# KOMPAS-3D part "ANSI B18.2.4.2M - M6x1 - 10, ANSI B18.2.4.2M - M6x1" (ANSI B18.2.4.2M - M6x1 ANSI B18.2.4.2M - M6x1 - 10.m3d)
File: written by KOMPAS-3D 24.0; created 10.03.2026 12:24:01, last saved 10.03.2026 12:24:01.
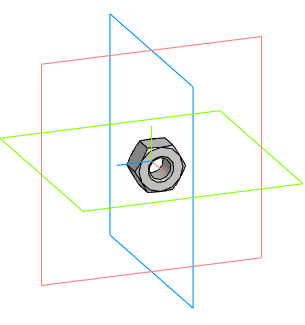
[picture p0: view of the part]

Document properties: Автор: R2D2; Полное имя файла: E:\Работа\Зайцев\BV3232P(4pc)-FP-3WL-F-ISO-H Кран шаровой DN.ru Ду15-100 Ру16\DN32\исходные материалы\ANSI B18.2.4.2M - M6x1 ANSI B18.2.4.2M - M6x1 - 10.m3d

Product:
- Body: Solid1  | qty 1
- Part/product: ANSI B18.2.4.2M - M6x1 - 10  | designation ANSI B18.2.4.2M - M6x1
    Комментарий: Типы метрических   шестигранных гаек   2
    additional columns: Сталь, мягкая

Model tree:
1. Solid1  (labels: Solid1)

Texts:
  ANSI B18.2.4.2M - M6x1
